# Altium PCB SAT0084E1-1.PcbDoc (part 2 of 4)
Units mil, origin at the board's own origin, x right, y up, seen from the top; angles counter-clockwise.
Board outline 7055 x 5555 mil, 6 copper layers (Top Layer, MidLayer1-GND, MidLayer2-HiSp, MidLayer3-GND, MidLayer4, Bottom Layer), stack 57.4 mil thick; 379 components, 207 nets, 1026 pads, 1546 vias.
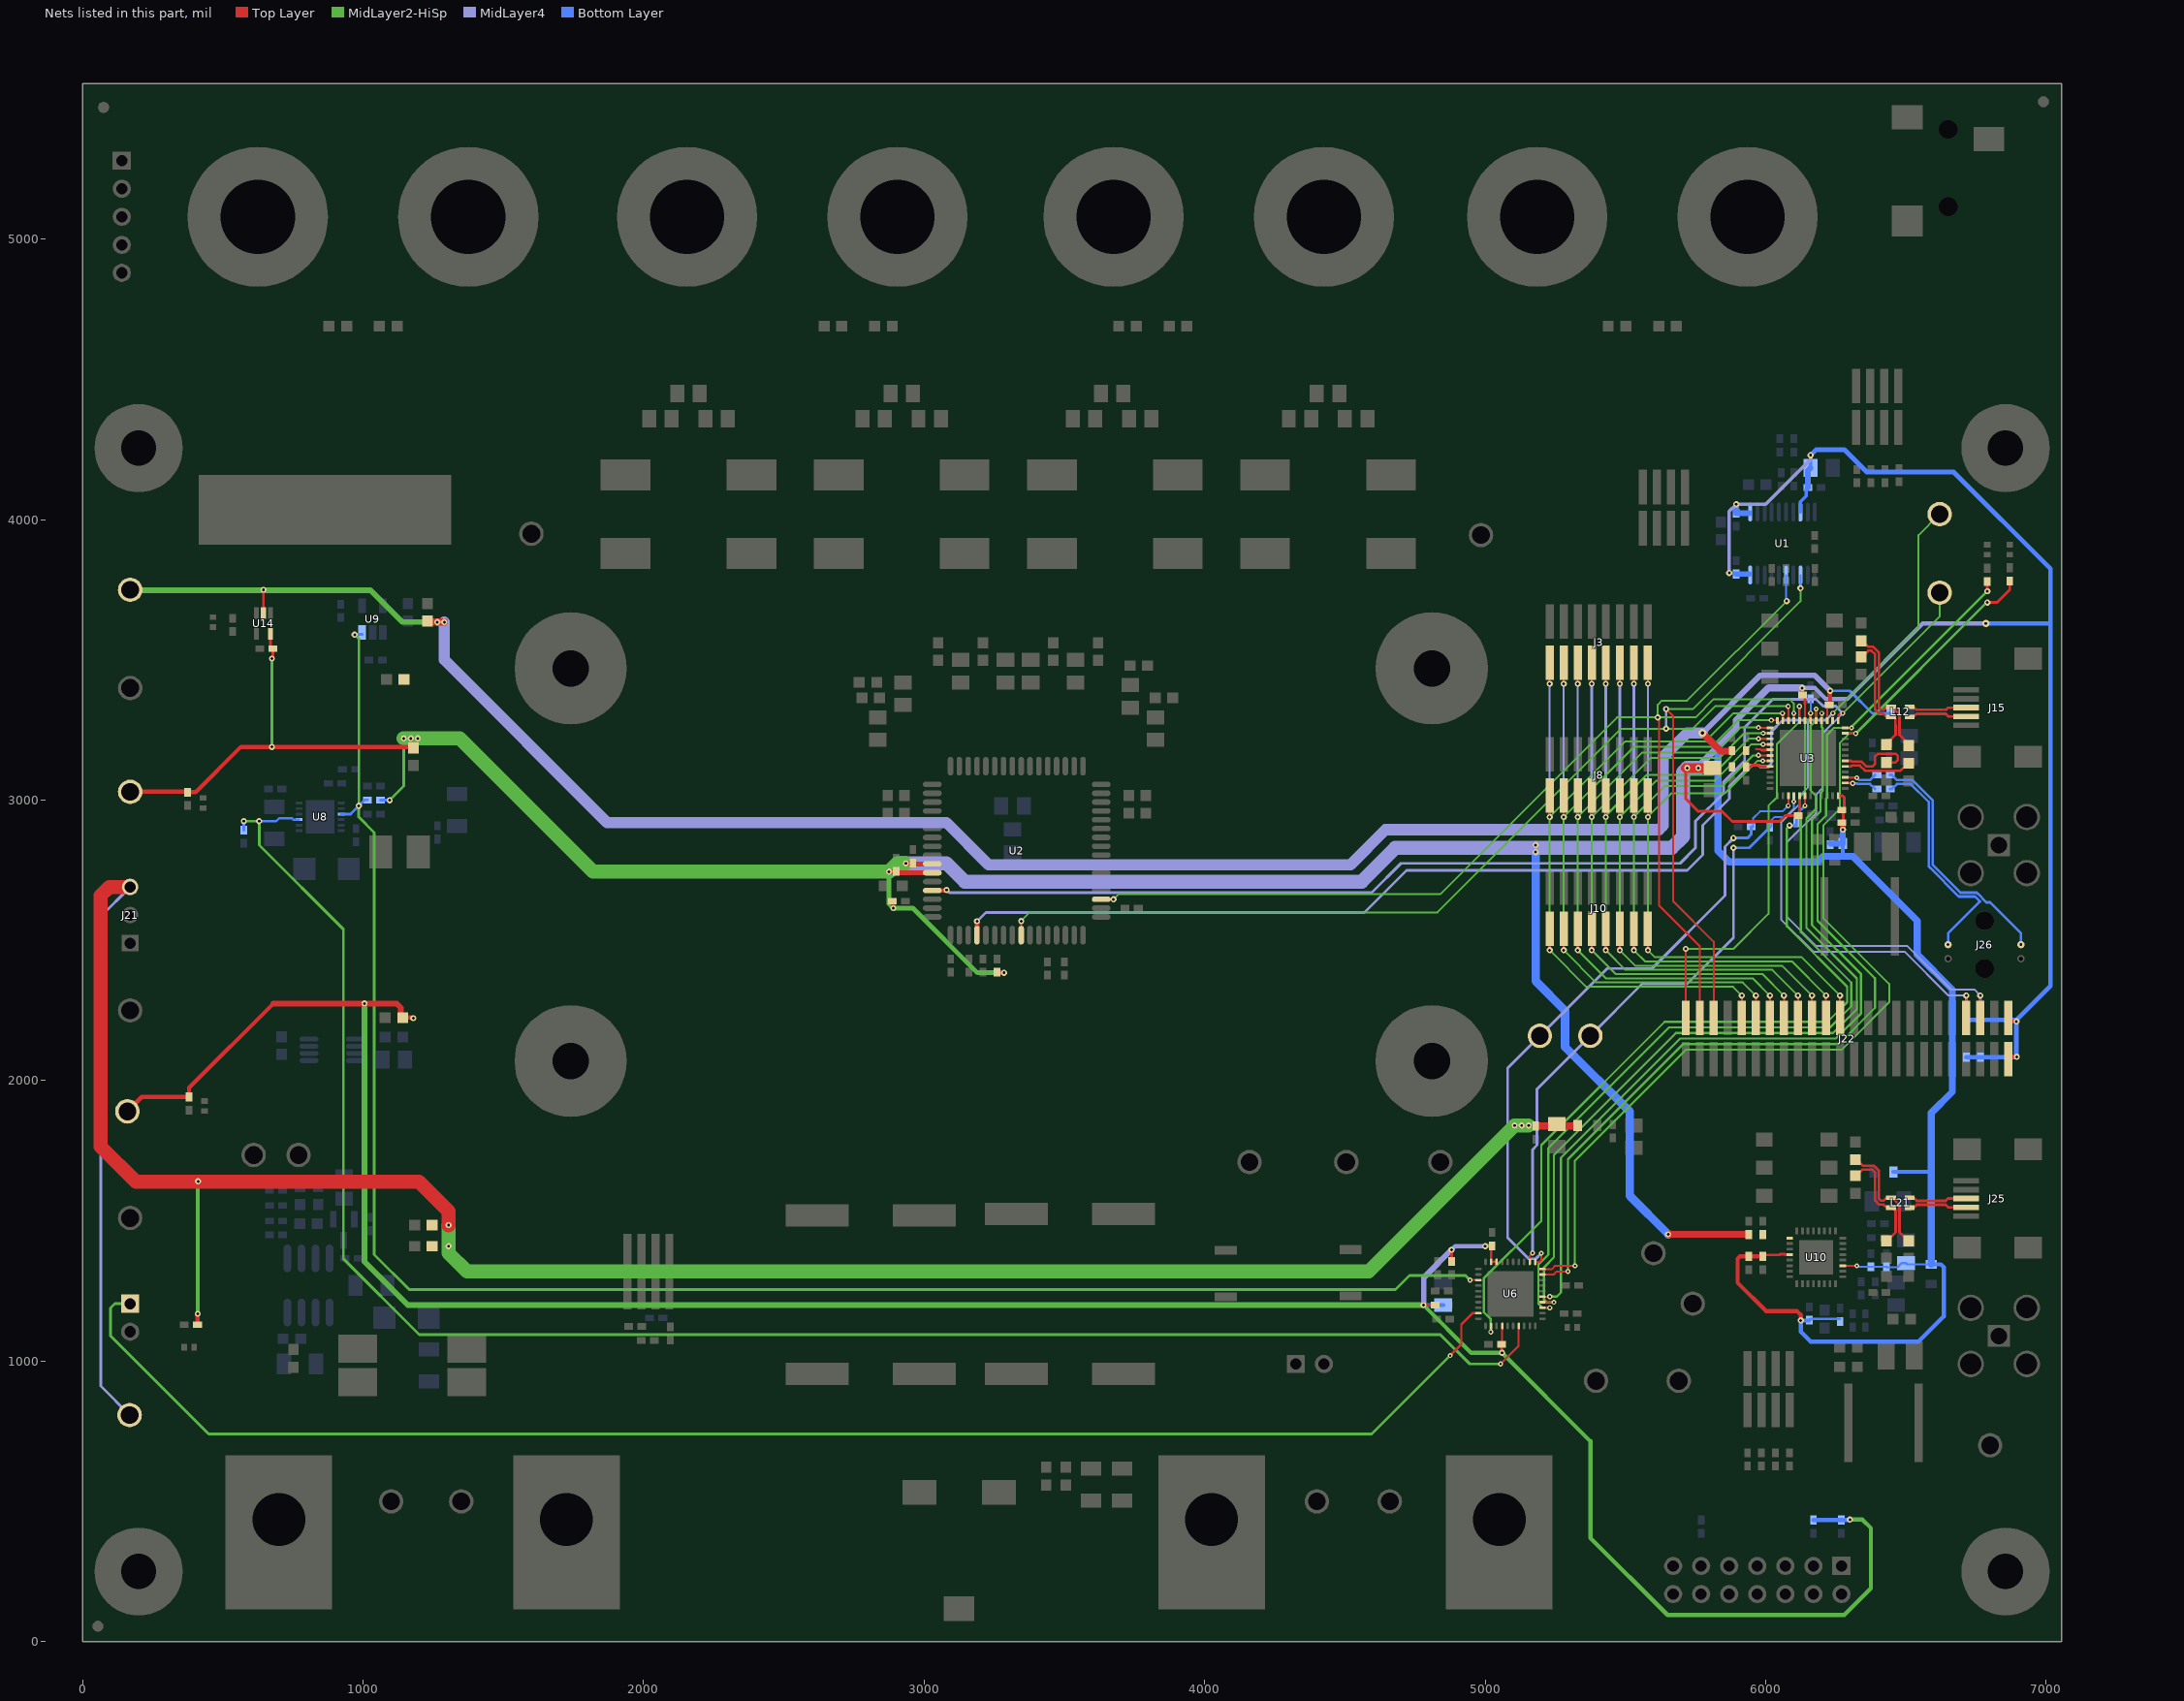
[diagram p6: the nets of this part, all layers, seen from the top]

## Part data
C1 C2 C3 C5 C18 C19 C24 C25 C43 C59 C61 C68 C71 C74 C77 C88 C96 C101 C105 C107 C112 C114 C116 C119 C127 C128: "CAP, CERM, 0.1uF, 10V, +/-10%, X7R, 0402"
C4 C87 C131: "CAP, CERM, 10uF, 10V, +/-10%, X7R, 0805"
C6 C7 C8 C9: "CAP, AL, 330uF, 50V, +/-20%, 0.12 ohm, SMD"
C10 C11 C92 C98: "CAP, CERM, 4.7uF, 50V, +/-10%, X7R, 1206"
C12: "CAP, CERM, 0.082uF, 50V, +/-10%, X7R, 0603"
C13: "CAP, CERM, 2200pF, 50V, +/-10%, X7R, 0603"
C14 C15 C16 C17: "CAP, CERM, 1uF, 25V, +/-10%, X7R, 0603"
C20 C21 C89: "CAP, CERM, 2200pF, 16V, +/-10%, X7R, 0402"
C22 C23 C102: "CAP, CERM, 2.2uF, 10V, +/-10%, X7R, 0603"
C26 C30: "CAP, CERM, 1uF, 50V, +/-10%, X7R, 0805"
C27 C32 C36 C40 C44 C48 C51 C55: "CAP, CERM, 1000pF, 50V, +/-5%, X7R, 0603"
C28 C31 C33 C37 C39 C41 C45 C47 C49 C52 C54 C56: "CAP, CERM, 0.47uF, 50V, +/-10%, X7R, 0805"
C29 C34 C38 C42 C46 C50 C53 C57: "CAP, CERM, 0.01uF, 50V, +/-5%, X7R, 0603"
C35: "CAP, CERM, 0.22uF, 16V, +/-10%, X7R, 0402"
C58 C62 C67 C69 C70 C72 C73 C76 C99 C103 C104 C108 C113 C115 C118: "CAP, CERM, 0.01uF, 16V, +/-10%, X7R, 0402"
C60 C64 C66 C75 C106 C117 C132: "CAP, CERM, 4.7uF, 16V, +/-10%, X7R, 0805"
C63 C65: "CAP, CERM, 0.1uF, 16V, +/-10%, X7R, 0402"
C78 C91 C100 C120: "CAP, CERM, 22uF, 10V, +/-10%, X7R, 1206"
C80 C81: "CAP, CERM, 0.1uF, 50V, +/-10%, X7R, 0402"
C82 C122: library part GRM188R71H104KA93D, "CAP, CERM, 0.1uF, 50V, +/-10%, X7R, 0603"
C84 C85 C124 C125 C130: "CAP, CERM, 0.1uF, 50V, +/-10%, X7R, 0603"
C86 C126: library part GRM188R71H473KA61D, "CAP, CERM, 0.047uF, 50V, +/-10%, X7R, 0603"
C90: "CAP, CERM, 1uF, 100V, +/-10%, X7R, 1206"
C93: "CAP, CERM, 150pF, 50V, +/-5%, C0G/NP0, 0603"
C94: "CAP, CERM, 0.015uF, 50V, +/-10%, X7R, 0603"
C95: "CAP, CERM, 1uF, 16V, +/-10%, X7R, 0603"
C97: "CAP, CERM, 0.022uF, 16V, +/-10%, X7R, 0402"
C109 C110 C111: "CAP, CERM, 1uF, 10V, +/-10%, X7R, 0603"
C129: library part GRM188R71C334KA01D, "CAP, CERM, 0.33uF, 16V, +/-10%, X7R, 0603"
D1: "LED, Orange, SMD"
D2 D4 D6 D7 D10: "LED, Yellow/green, SMD"
D3 D5: "Diode, Schottky, 60V, 1A, SMA"
D8: "LED, Blue, SMD"
D9: "Diode, Schottky, 30V, 0.2A, SOT-23"
FID1 FID2 FID3 FID4 FID5 FID6: "Fiducial mark.  There is nothing to buy or mount."
H1 H2 H3 H4: library part "NY PMS 440 0025 PH", "Machine Screw, Round, #4-40 x 1/4, Nylon, Philips panhead"
H5 H6 H7 H8: library part 1902C, "Standoff, Hex, 1 1/16\"L #4-40 Nylon"
H9: library part V5583K, "Heatsink, requires 2 M3 screw Mounting hole per rails"
H10 H11 H12 H13: library part "MPMS 003 0005 PH", "MACHINE SCREW PAN PHILLIPS M3 10mm"
H14 H15 H16 H17: library part 1902C, "ROUND SPACER M3 PVC 1.4MM"
J1 J2 J18 J20: library part CB35-36-CY, "Terminal 50A Lug"
J3 J8 J10: library part FTS-108-02-L-DV, "Header, 8x2, 1.27mm"
J4: "Connector, Audio Jack, 3.5mm, Stereo, SMD"
J5 J13 J16 J19: library part FTS-104-02-L-DV, "Header, 4x2, 1.27mm"
J6: library part TSW-105-07-G-S, "Header, TH, 100mil, 5x1, Gold plated, 230 mil above insulator"
J7 J9 J11 J12: library part 2269-0, "Connector, Banana Jack, Double, Black Base, 15A, TH"
J14 J23: "RIGHT ANGLE PLUG FOR PCB"
J15 J25: "Connector, Receptacle, Mini-USB 2.0, Type AB, R/A, SMT"
J17: library part SBH11-PBPC-D07-ST-BK, "Header (shrouded), 100 mil, 7x2, Gold plated, TH"
J21: library part PEC03SAAN, "Header, 100mil, 3x1, Tin plated, TH"
J22: "Header, 24x2, 1.27mm"
J24 J27: library part TSW-102-07-G-S, "Header, TH, 100mil, 2x1, Gold plated, 230 mil above insulator"
J26: "Double Compliant Coax Assembly"
L1: "Inductor, Shielded E Core, Ferrite, 10uH, 7.2A, 0.01 ohm, SMD"
L2 L3 L4 L5: "Inductor, Shielded, Ferrite, 10uH, 3A, 0.022 ohm, SMD"
L6 L7 L8 L16 L17: library part BEAD-BLM18AG_SERIES, "Ferrite Chip, 400 mA, ±25%"
L9: library part MSS7341T-104MLB, "Inductor, Shielded Drum Core, Ferrite, 100uH, 0.7A, 0.28 ohm, SMD"
L10 L19: library part IND_1008PS-XXXMC, "Inductor, 5.6uH, 1.5A, 0.36 ohm, SMD"
L11 L20: "Inductor, Wirewound, Ferrite, 165uH, 0.65A, 0.46 ohm, SMD"
L12 L21: library part DLW21SN900HQ2L, "Coupled inductor, 0.3A, 0.4 ohm, +/-25%, SMD"
L13: "Coupled inductor, 68uH, 1.35A, 0.2 ohm, +/-20%, SMD"
L14: "Inductor, Shielded, Ferrite, 10uH, 1.05A, 0.083 ohm, SMD"
L18: "Inductor, Shielded Drum Core, Ferrite, 100uH, 0.7A, 0.28 ohm, SMD"
LBL1: library part THT-14-423-10, "Thermal Transfer Printable Labels, 0.650\" W x 0.200\" H - 10,000 per roll"
Logo1: library part TI_Logo, "Texas Instrument Corporate Signature"
R1 R2 R4 R5 R6 R19 R20 R25 R32 R43 R48 R54 R59 R74 R92 R107: "RES, 10k ohm, 5%, 0.063W, 0402"
R3: "RES, 133 ohm, 1%, 0.063W, 0402"
R7 R8: "RES, 470 ohm, 5%, 0.063W, 0402"
R9: "RES, 20k ohm, 5%, 0.063W, 0402"
R10 R21 R22 R41: "RES, 47k ohm, 5%, 0.063W, 0402"
R11 R12 R13 R14 R15 R16 R17 R18: "RES, 5.60 ohm, 1%, 0.33W, 0805"
R23 R24 R72 R73: "RES, 4.7k ohm, 5%, 0.063W, 0402"
R26 R27: library part CRCW0402220RJNED, "RES, 220 ohm, 5%, 0.063W, 0402"
R28: "RES, 220 ohm, 5%, 0.063W, 0402"
R29 R30 R86 R87: "RES, 1.0k ohm, 5%, 0.1W, 0603"
R31 R88: library part CRCW06030000Z0EA, "RES, 0 ohm, 5%, 0.1W, 0603"
R33 R37 R44 R45 R58 R64 R65 R93 R95 R108: "RES, 0 ohm, 5%, 0.1W, 0603"
R34: "RES, 475 ohm, 1%, 0.063W, 0402"
R35 R62 R66 R67: "RES, 365 ohm, 1%, 0.063W, 0402"
R36 R89 R97 R99: "RES, 10.0k ohm, 1%, 0.063W, 0402"
R38 R91: "RES, 0 ohm, 5%, 0.063W, 0402"
R39: "RES, 11.0k ohm, 1%, 0.063W, 0402"
R40 R47 R96: "RES, 49.9 ohm, 1%, 0.063W, 0402"
R46: "RES, 1.0 ohm, 5%, 0.1W, 0603"
R49: "RES, 1.96k ohm, 1%, 0.063W, 0402"
R50: "RES, 11.5k ohm, 1%, 0.1W, 0603"
R51 R63: "RES, 9.76k ohm, 1%, 0.063W, 0402"
R52: "RES, 1.82k ohm, 1%, 0.063W, 0402"
R53: "RES, 28.0k ohm, 1%, 0.063W, 0402"
R56: "RES, 44.2k ohm, 1%, 0.063W, 0402"
R57 R94: "RES, 100k ohm, 5%, 0.063W, 0402"
R60: "RES, 3.16k ohm, 1%, 0.063W, 0402"
R61: "RES, 0.39 ohm, 1%, 0.125W, 0402"
R90: "RES, 2.00k ohm, 1%, 0.063W, 0402"
R98: "RES, 5.36k ohm, 1%, 0.063W, 0402"
R100: "RES, 18.7k ohm, 1%, 0.063W, 0402"
R103 R105: "RES, 100k ohm, 1%, 0.063W, 0402"
R104: "RES, 3.01k ohm, 1%, 0.063W, 0402"
R106: "RES, 14.0k ohm, 1%, 0.063W, 0402"
S1 S5: library part SKRKAEE010, "Switch, Push Button, SMD"
SH-J3 SH-J5 SH-J8 SH-J10 SH-J13 SH-J16 SH-J19 SH-J22a SH-J22b SH-J22c SH-J22d SH-J22e SH-J22f SH-J22g SH-J22h SH-J22i SH-J22j SH-J22k SH-J22l SH-J22m SH-J22n SH-J22o SH-J22p SH-J22q SH-J22r SH-J22s SH-J22t SH-J22u SH-J22v SH-J22w SH-J22x: "CONN JUMPER SHORTING 1.27MM GOLD"
SH-J21 SH-J24 SH-J27: "Shunt, 100mil, Gold plated, Black"
TP1 TP10 TP11 TP15 TP16 TP18 TP19: library part 5005, "Test Point, Compact, Red, TH"
TP2 TP3 TP4 TP9 TP14 TP17 TP41 TP48: library part 5006, "Test Point, Compact, Black, TH"
TP5 TP6 TP7 TP8 TP23 TP24 TP37 TP38 TP54 TP55: library part 5007, "Test Point, Compact, White, TH"
TP12: library part 5009, "Test Point, Compact, Yellow, TH"
TP13: library part 5008, "Test Point, Compact, Orange, TH"
U1: "2-VRMS DirectPath™, 112, 106, 100-dB Audio Stereo DAC with 32-bit, 384-kHz PCM Interface, PW0020A"
U2: library part "Digital Input Four-Channel Automotive Digital Amplifier", "There is nothing to buy or mount."
U3: "IC SER/DESER 10-50MHZ 8B 48-WQFN"
U6: "MSP430F22x2  Automotive  Mixed-Signal  Microcontrollers"
U7: "LM5001x  High-Voltage  Switch-Mode  Regulator"
U8: "LM34919C Ultra Small 42V, 600 mA Constant On-Time Buck Switching Regulator, DNT0012B"
U9: "LDO Voltage Regulators Ultra Lo Noise Hi PSRR Fast RF 200mA"
U10: "Multi-Channel Digital Audio Link, RTV0032A"
U13: library part LM2936MM-3.3/NOPB, "Ultra-Low Quiescent Current LDO Voltage Regulator, 8-pin Mini SOIC, Pb-Free"
U14: "IC BUS BUFF GATE 3ST SGL SC70-5"
ZZ1: library part AssemblyNoteLabel
ZZ2 ZZ3 ZZ4 ZZ5 ZZ6 ZZ7: library part AssemblyNote

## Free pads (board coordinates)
  round 400 / inner round 200 / far side round 400 hole 130: 0(1740,2070) 0(1740,3470) 0(4810,2070) 0(4810,3470)

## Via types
v1: diameter 22, hole 10, Top Layer to Bottom Layer, tented both sides, 1179 vias
v2: diameter 48, hole 22, Top Layer to Bottom Layer, tented both sides, 128 vias
v3: diameter 32, hole 16, Top Layer to Bottom Layer, tented both sides, 112 vias
v4: diameter 18, hole 8, Top Layer to Bottom Layer, tented both sides, 80 vias
v5: diameter 19.68, hole 7.87, Top Layer to Bottom Layer, tented both sides, 30 vias
v6: diameter 26, hole 16, Top Layer to Bottom Layer, 12 vias
v7: diameter 36, hole 16, Top Layer to Bottom Layer, tented both sides, 2 vias
v8: diameter 26, hole 10, Top Layer to Bottom Layer, tented both sides, 1 vias
v9: diameter 20, hole 8, Top Layer to Bottom Layer, tented both sides, 1 vias
v10: diameter 30, hole 12, Top Layer to Bottom Layer, tented both sides, 1 vias

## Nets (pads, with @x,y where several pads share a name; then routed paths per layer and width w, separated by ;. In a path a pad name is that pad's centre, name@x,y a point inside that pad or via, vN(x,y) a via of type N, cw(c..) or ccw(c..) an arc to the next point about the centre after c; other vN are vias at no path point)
1V8: C58.1 C59.1 C67.1 C68.1 C70.1 C71.1 C104.1 C105.1 C106.1 C113.1 C114.1 L7.1 L8.1 L16.1 L17.1 R36.2 R65.2 R89.2 R92.2 TP18.1 U3.3 U3.17 U3.36 U10.11 U10.28 U14.2 | length 12576.4
  Top Layer w7: 5965,3183 5966,3182 ; 5983.79,3178.21 5986,3178.21 ; U3.3@6218.9,3283.86 6219.5,3284.46 6219.5,3333.12 C70.1@6226.38,3340
  Top Layer w8: 5966,3182 5980,3182 5983.79,3178.21 ; U10.11@6274.49,1340.47 6274.96,1340 v4(6325,1340)
  Top Layer w10: U14.2@645,3675 v1(645,3750) ; 5986,3178.21 5999.49,3178.21 6000.8,3179.53 U3.17@6016.14,3179.53 ; C113.1@5990,1373.62 5995.38,1379 6048.7,1379 6049.7,1380 6050.3,1380 6051.3,1381 6069,1381 6070.16,1379.84 U10.28@6085.51,1379.84 ; U3.36@6258.27,3016.14 6273.86,3016.14 6280,3010 6280,2968.62 6276.38,2965 C68.1@6276.38,2920
  Top Layer w15: C113.1@5990,1373.62 C114.1@5940,1373.62 5908.62,1373.62 5900,1365 5900,1280 6001,1179 6111,1179 6125,1165 v1@6125,1150 ; v1@6225,3390 6230,3385 6230,3343.62 C70.1@6226.38,3340
  Top Layer w20: v1(6275,2895) 6275,2918.62 C68.1@6276.38,2920
  Top Layer w25: R65.2@1230,3638.5 1233.5,3635 v1(1265,3635) v1(1290,3635) ; v10(5775,3240) 5840,3175 5878.62,3175 C59.1@5880,3176.38
  MidLayer2-HiSp w20: TP18.1@170,3748.62 1026.38,3748.62 1140,3635 v1@1261.5,3635
  MidLayer4 w20: v10(5775,3240) 5980,3445 6175,3445 v1@6225,3395
  MidLayer4 w25: v1(1265,3635) v1(1290,3635)
  MidLayer4 w40: v1(1290,3635) 1290,3500 1870,2920 3080,2920 3230,2770 4520,2770 4645,2895 5620,2895 5635,2910 5635,3155 5720,3240 v10(5775,3240)
  Bottom Layer w8: R89.2@6155,1146.38 6159.43,1150.81 6264.43,1150.81 R92.2@6265,1151.38 ; v4(6325,1340) 6328.62,1336.38 C104.1@6375,1336.38 C105.1@6430,1336.38 6431.38,1335 6470,1335 6485,1350 C106.1@6500,1350 6505,1345 L16.1@6590,1345
  Bottom Layer w10: C71.1@6226.38,3340 6226.38,3388.62 6225,3390 6300,3390 6380,3310 L7.1@6445,3310
  Bottom Layer w15: R89.2@6155,1146.38 6153.62,1145 v1(6125,1145) 6125,1105 6160,1070 6545,1070 6635,1160 6635,1335 6625,1345 L16.1@6590,1345 ; 6275,2800 L8.1@6275,2845 ; L17.1@6455,1675 6590,1675
  Bottom Layer w20: R36.2@6230,2846.38 6231.38,2845 L8.1@6275,2845 v1(6275,2895)
  Bottom Layer w25: v10(5775,3240) 5830,3185 5830,2820 5870,2780 6185,2780 6205,2800 6275,2800 6310,2800 6540,2570 6540,2450 6665,2325 6665,1960 6590,1885 6590,1675 L16.1@6590,1345
  other v1: 6230,3390
3V3: C1.1 C2.1 C3.1 C4.1 C5.1 C18.1 C60.1 C61.1 C62.1 C69.1 C72.1 C107.1 C108.1 C112.1 J22.47 J22.48 R21.2 R22.2 R23.2 R24.2 R58.2 R59.1 R62.2 R64.1 R72.2 R73.2 TP16.1 U1.1 U1.8 U1.20 U2.58 U2.59 U3.7 U3.20 U3.29 U10.25 U14.5 | length 16477.5
  Top Layer w7: U3.7@6140.5,3284.2 6140.5,3343.83
  Top Layer w8: C72.1@6118.62,2945 6120,2946.38 6120,3015.67 U3.29@6120.47,3016.14
  Top Layer w9: U14.5@670,3595 670,3548.62 C112.1@678.62,3540 ; v1(675,3505) 678.62,3508.62 C112.1@678.62,3540 ; C112.1@675,3536.38 C112.1@678.62,3540 ; 5970,3125 5974.99,3125 5980.49,3119.5 6015.17,3119.5 U3.20@6016.14,3120.47 ; C62.1@6133.62,3375 6140.16,3368.46 6140.16,3344.18 6140.5,3343.83 ; U3.7@6140.16,3283.86 U3.7@6140.5,3284.2
  Top Layer w10: v1@5715,3115 5715,3005 5760,2960 5845,2960 5881,2924 6049,2924 6070,2945 C72.1@6116.38,2945 ; C69.1@5934.38,3123 C69.1@5930,3118.62 5943.62,3118.62 5950,3125 5970,3125
  Top Layer w15: TP16.1@170,3030 373.62,3030 R62.2@375,3028.62 403.62,3028.62 565,3190 v1(675,3190) 1165,3190 R58.2@1175,3180 ; v1(6130,3400) 6130,3378.62 C62.1@6133.62,3375 ; J22.47@6865,2076.48 J22.47@6872.15,2083.62 ; J22.48@6865,2223.52 J22.48@6872.15,2216.38 ; J22.47@6872.15,2085 v1(6895,2085) ; J22.48@6872.15,2211.38 v1(6893.62,2211.38)
  Top Layer w17: v1(2875,2745) 2898.62,2745 C5.1@2900,2746.38 ; R22.2@2886.38,2640 2890,2636.38 v1(2890,2615) ; C5.1@2900,2751.38 C5.1@2900,2746.38 ; v1(2935,2775) 2958.62,2775 C18.1@2960,2776.38 ; C18.1@2960,2772.76 U2.58@3029.13,2772.76 ; U2.59@3029.13,2741.26 2900,2741.26 C5.1@2900,2746.38 ; R21.2@3260,2386.38 3261.38,2385 v1(3285,2385)
  Top Layer w25: v1(5652.5,1452.5) 5938.88,1452.5 C107.1@5940,1451.38
  Top Layer w35: v1@5715,3115 C60.1@5810,3115
  MidLayer2-HiSp w9: v1(675,3190) v1(675,3505)
  MidLayer2-HiSp w10: v1(1095,3000) 1145,3050 v1(1145,3220)
  MidLayer2-HiSp w17: v1(2875,2745) 2875,2630 v1(2890,2615) 2960,2615 3190,2385 v1(3285,2385)
  MidLayer2-HiSp w50: v1(1145,3220) v1(1170,3220) v1(1195,3220) ; v1@1205,3220 1345,3220 1820,2745 v1(2875,2745) 2905,2775 v1(2935,2775)
  MidLayer4 w12: v1(5870,3810) 5870,4030 v1(5895,4055) 6000,4055 6160,4215 v1(6160,4230)
  MidLayer4 w15: v1(6130,3400) 6175,3400 6215,3360 6290,3360 6560,3630 v8(6785,3630)
  MidLayer4 w25: v1@5755,3115 5895,3255 5895,3285 6010,3400 v1(6130,3400)
  MidLayer4 w50: v1(2875,2745) 2905,2775 v1(2935,2775) 3080,2775 3145,2710 4560,2710 4680,2830 5665,2830 5705,2870 5705,3100 v1(5720,3115) v1(5760,3115)
  Bottom Layer w10: R59.1@1062.81,3000.56 1094.44,3000.56 v1(1095,3000)
  Bottom Layer w12: v1(5870,3810) 5891.38,3810 C2.1@5895,3806.38 ; U1.8@6123.98,4027.2 6123.98,4063.98 6145,4085 6145,4110 C3.1@6150,4115 ; C4.1@6160,4185 v1(6160,4230)
  Bottom Layer w15: R72.2@6715,2083.62 R73.2@6765,2083.62 v1@6895,2083.62 ; R23.2@6715,2216.38 R24.2@6765,2216.38 6893.62,2216.38 v1@6895,2215 ; v8(6785,3630) 7015,3630
  Bottom Layer w17: v1(6160,4230) 6180,4250 6280,4250 6360,4170 6670,4170 7015,3825 7015,2337.76 6893.62,2216.38 v1@6893.62,2085
  Bottom Layer w20: C2.1@5895,3806.38 U1.20@5941.26,3806.38 ; v1(5895,4055) C1.1@5895,4023.62 U1.1@5941.26,4023.62 ; C3.1@6150,4115 6150,4175 C4.1@6160,4185
  Bottom Layer w30: v1(5180,2840) 5180,2355 5285,2250 5285,2120 5515,1890 5515,1590 v1(5652.5,1452.5)
  other v1: 5180,2815
3V3_ENA: R57.2 U6.17 U8.3 | length 6362.4
  Top Layer w7: v4(5055,990) 5119,1054 5119,1083 5119.53,1083.53 U6.17@5119.53,1125.83
  MidLayer2-HiSp w10: v1(575,2925) v1(630,2925) 630,2840 930,2540 930,1365 1200,1095 4840,1095 4945,990 v4(5055,990)
  Bottom Layer w8: v1(630,2925) 691,2925 702,2936 747,2936 752.29,2930.71 U8.3@772.1,2930.71
  Bottom Layer w10: R57.2@575,2893.62 v1(575,2925)
3V3_MCU: C87.1 C88.1 C128.1 R26.1 R27.1 R41.2 R43.2 R45.2 R66.2 TP19.1 U6.14 U6.38 U6.39 | length 9449.8
  Top Layer w8: v1@5058.62,1031.38 v1(5060,1030) ; C128.1@5058.62,1060 5060.47,1061.85 U6.14@5060.47,1125.83
  Top Layer w9: C88.1@5021.1,1417.48 5021.1,1411.38 U6.39@5021.1,1354.17 U6.38@5040.79,1354.17
  Top Layer w10: v1(4780,1200) R41.2@4821.38,1200 R41.2@4826.38,1200 ; R43.2@4880,1355.28 v1(4880,1397) ; v1@5058.62,1031.38 C128.1@5058.62,1060
  Top Layer w15: TP19.1@159.87,1890.5 211.61,1942.24 R66.2@380,1942.24 380,1975 680,2275 ; R45.2@1135,2231.5 R45.2@1141.5,2225 1177,2225 v1(1179,2223) ; v1(5000,1410) 5001.38,1411.38 5021.1,1411.38 C88.1@5025,1411.38
  Top Layer w20: 680,2275 1120,2275 1135,2260 R45.2@1135,2231.5
  MidLayer2-HiSp w15: v1(4780,1200) 4950,1030 v1(5060,1030) 5375,715 5375,370 5650,95 6280,95 6375,190 6375,405 6345,435 v1(6300,435)
  MidLayer2-HiSp w20: v1(1005,2275) 1005,1355 1160,1200 v1(4780,1200) v1@4781,1201
  MidLayer4 w15: v1(4880,1397) 4893,1410 v1(5000,1410)
  MidLayer4 w20: v1@4781,1201 4781,1298 v1(4880,1397)
  Bottom Layer w15: v1(4780,1200) C87.1@4850,1200 ; R27.1@6170,433.62 R26.1@6270,433.62 6298.62,433.62 v1(6300,435)
3V3_PGD: R59.2 U6.3 U8.9 U9.3 | length 6395.7
  Top Layer w7: v4(4945.83,1289.21) U6.3@4975.83,1289.21
  MidLayer2-HiSp w9: v1(970,3590) 985,3575 v1(985,2980)
  MidLayer2-HiSp w10: v1(985,2980) 985,2940 1040,2885 1040,1380 1165,1255 4680,1255 4730,1305 4930.04,1305 v4(4945.83,1289.21)
  Bottom Layer w9: U8.9@921.71,2950.4 955.4,2950.4 v1(985,2980) 1005.56,3000.56 R59.2@1015.57,3000.56 ; v1(970,3590) 971.17,3591.17 U9.3@996.76,3591.17
8V: C63.1 C64.1 C129.1 J21.3 L6.1 R49.2 R108.2 TP11.1 | length 9223.2
  Top Layer w15: R49.2@409.82,1130 409.82,1167.82 v1(411,1169)
  Top Layer w25: C63.1@5180,1838.62 5323.62,1838.62 L6.1@5330,1845
  Top Layer w50: J21.3@169.87,2690.5 95.5,2690.5 65,2660 65,1765 190,1640 1200,1640 1305,1535 v1(1305,1485)
  MidLayer2-HiSp w15: v1(411,1169) 411,1640 v1(412,1641)
  MidLayer2-HiSp w50: v1(1305,1485) v1(1305,1410) 1305,1385 1370,1320 4585,1320 v1(5105,1840) v1(5130,1840) v1(5155,1840)
  MidLayer4 w10: TP11.1@168,808 65,911 65,2585.64 J21.3@169.87,2690.5
8V_ENA: J24.1 U6.9 | length 5417.2
  Top Layer w8: v4(4875,1020) 4915,1060 4915,1131 4955.1,1171.1 U6.9@4975.83,1171.1
  MidLayer2-HiSp w10: J24.1@170,1205 115,1205 100,1190 100,1090 450,740 4595,740 v4(4875,1020)
CMLOUT_N: C81.2 U3.39 | length 117.4
  Top Layer w9: U3.39@6283.86,3081.1 6320,3081.1 6321.1,3080 v4(6325,3080)
  Bottom Layer w9: v4(6325,3080) 6333,3072 6372,3072 C81.2@6390,3090
CMLOUT_P: C80.1 U3.38 | length 113
  Top Layer w9: U3.38@6283.86,3061.42 v4@6308.58,3061.42
  Bottom Layer w9: v4(6310,3060) 6325.2,3060 6327.2,3058 6372,3058 C80.1@6390,3040
CMLOUTC_N: C81.1 J26.1 | length 875.2
  Bottom Layer w9: C81.1@6443.62,3090 6450,3090 6468,3072 6523,3072 6594.9,3000.1 6594.9,2769.9 6694.3,2670.5 6752.3,2670.5 6756.4,2666.4 6787,2635.8 6799.2,2635.8 6909.92,2525.08 J26.1@6909.92,2485.04
CMLOUTC_P: C80.2 J26.2 | length 837.4
  Bottom Layer w9: C80.2@6443.62,3040 6450,3040 6468,3058 6517.2,3058 6580.9,2994.3 6580.9,2764.1 6585,2760 6688.5,2656.5 6746.5,2656.5 6764,2639 6650.08,2525.08 J26.2@6650.08,2485.04
DESER_BISTEN: R19.1 U3.6 U6.23 | length 3146.8
  Top Layer w7: U6.23@5204.17,1190.79 5229.21,1190.79 v4(5230,1190) ; U3.6@6159.84,3283.86 6159.84,3309.84 v4(6160,3310)
  MidLayer2-HiSp w8: v4(5230,1190) 5205,1190 5190,1205 5190,1345 5225,1380 5225,1760 5655,2190 6230,2190 6305,2265 6305,2350 6125,2530 6125,2945 6120,2950 6120,3010 6140,3030 6140,3275 6160,3295 v4(6160,3310)
  Bottom Layer w7: v4(6160,3310) R19.1@6160,3361.38
DESER_DIN_N: C85.1 C86.1 U3.42 | length 291.8
  Top Layer w9: U3.42@6283.86,3140.16 6304,3140.16 6306.84,3137.31 6341.48,3137.31 6358.8,3120 6380,3120 6390,3130 6390,3156 6399,3165 6464,3165 6471,3158 6471,3143 6462.5,3134.5 C85.1@6430,3134.5
DESER_DIN_P: C82.1 C84.1 U3.41 | length 240.3
  Top Layer w9: U3.41@6283.86,3120.47 6304,3120.47 6306.84,3123.31 6335.69,3123.31 6354,3105 6480,3105 ; 6485,3110 6480,3105 ; C82.1@6500,3125 6480,3105
DESER_GPI2: R20.1 TP54.1 U3.27 U6.31 | length 2367.6
  Top Layer w7: U6.31@5178.58,1354.17 5194.17,1354.17 5200,1360 v4(5200,1385) ; v4(6080,2980) 6080.5,2980.5 6080.5,3015.54 U3.27@6081.1,3016.14
  MidLayer4 w10: v4(5200,1385) 5180,1365 5155,1365 5080,1440 5080,2045 TP54.1@5195,2160 5435,2400 5595,2400 5855,2660 5855,2835 v1(5885,2865)
  Bottom Layer w7: R20.1@5955,2903.62 5955,2935 5980,2960 6060,2960 v4(6080,2980)
  Bottom Layer w10: v1(5885,2865) 5935,2865 5948.62,2878.62 R20.1@5948.62,2905
DESER_GPI3: R54.1 TP55.1 U3.28 U6.32 | length 2201.5
  Top Layer w7: U6.32@5158.9,1354.17 5158.9,1375.9 v4(5169,1386) ; v4(6100,2995) 6100.79,2995.79 U3.28@6100.79,3016.14
  MidLayer4 w10: v4(5169,1386) 5169,1754 5185,1770 5185,1970 TP55.1@5375,2160 5560,2345 5720,2345 5885,2510 v1(5885,2830)
  Bottom Layer w7: R54.1@6015,2903.62 6020,2908.62 6020,2928.62 6031.38,2940 6070,2940 6099.5,2969.5 6099.5,2994.5 v4(6100,2995)
  Bottom Layer w10: v1(5885,2830) 5941.38,2830 R54.1@6015,2903.62
DESER_I2C_SCL: J22.42 R23.1 TP7.1 U2.4 U3.2 | length 6106.2
  Top Layer w7: U3.2@6238.58,3283.86 v4@6238.58,3309.58 ; J22.42@6715,2223.52 v1(6715,2303.52)
  Top Layer w10: v4@6238.58,3309.58 v4(6239,3310)
  Top Layer w17: U2.4@3188.58,2518.82 v1(3188.58,2568.58) v1@3190,2570
  MidLayer2-HiSp w7: v4(6239,3310) 6545,3616 6545,3945 TP7.1@6620,4020
  MidLayer4 w7: 6152,3285 6150,3283 6150,3045 6120,3015 6120,2985 6055,2920 6055,2575 6170,2460 6495,2460 6651.48,2303.52 v1(6715,2303.52)
  MidLayer4 w10: v1(3188.58,2568.58) 3220,2600 4570,2600 4720,2750 5720,2750 5775,2805 5775,2910 5870,3005 5870,3050 5945,3125 5975,3125 5981,3119 6009,3119 6020,3130 6020,3245 6060,3285 6214,3285 v4(6239,3310)
  Bottom Layer w10: R23.1@6715,2263.62 v1(6715,2303.52)
DESER_I2C_SDA: J22.44 R24.1 TP8.1 U2.61 U3.1 | length 6052.8
  Top Layer w7: U3.1@6258.27,3283.86 6258.5,3284.09 6258.5,3303.5 6265,3310 v4(6275,3310) ; J22.44@6765,2223.52 v1(6765,2303.52)
  Top Layer w15: U2.61@3029.13,2678.27 3078.27,2678.27 v1(3080,2680)
  MidLayer2-HiSp w7: v4(6275,3310) 6620,3655 TP8.1@6620,3740
  MidLayer4 w7: v4(6275,3310) 6202,3237 6202,3042 6180,3020 6180,2955 6075,2850 6075,2585 6180,2480 6505,2480 6660,2325 6706.07,2325 ; 6706.09,2325.02 6723.91,2325.02 ; 6723.93,2325 6743.52,2325 v1(6765,2303.52)
  MidLayer4 w10: v1(3080,2680) 3090,2670 4595,2670 4700,2775 5695,2775 5750,2830 5750,2925 5850,3025 5850,3065 5925,3140 5925,3260 6025,3360 6180,3360 6205,3335 6250,3335 v4(6275,3310)
  Bottom Layer w10: R24.1@6765,2263.62 v1(6765,2303.52)
DESER_I2S_BCK: J22.6 U1.13 U2.9 U3.10 | length 5129.7
  Top Layer w7: v1@3345,2570 v1(3346.06,2568.94) U2.9@3346.06,2518.82 ; v1(5645,3325) 5670,3300 5670,2640 5815,2495 J22.6@5815,2223.52 ; v4(6080,3335) 6080.5,3334.5 6080.5,3284.46 U3.10@6081.1,3283.86
  MidLayer2-HiSp w7: v1(3346.06,2568.94) 3377.13,2600 4830,2600 5485,3255 5740,3255 5820,3335 v4(6080,3335) ; v1(5645,3325) 5740,3325 6123.98,3708.98 v1(6123.98,3756.02)
  MidLayer4 w7: v1(5645,3255) v1(5645,3325)
  Bottom Layer w7: U1.13@6123.98,3802.8 v1(6123.98,3756.02) v1@6125,3755
DESER_I2S_DATA0: J3.1 J8.1 J10.1 J22.10 U3.11 | length 3019.8
  Top Layer w7: v1(5230,2465) J10.1@5230,2541.48 ; v1(5230,2940) J8.1@5230,3016.48 ; v1(5230,3415) J3.1@5230,3490 ; J22.10@5915,2223.52 v1(5915,2303.52) ; v4(6060,3310) 6061.42,3308.58 U3.11@6061.42,3283.86
  MidLayer2-HiSp w7: v1(5230,2465) v1(5230,2940) 5500,3210 5785,3210 5885,3310 v4(6060,3310) ; v1@5235,2460 5360,2335 5883.52,2335 v1(5915,2303.52) v1@5920,2298.52
  MidLayer4 w7: v1(5230,2940) v1(5230,3415)
DESER_I2S_DATA1: J3.3 J8.3 J10.3 J22.12 U3.12 | length 2914.9
  Top Layer w7: v1(5280,2465) J10.3@5280,2541.48 ; v1(5280,2940) J8.3@5280,3016.48 ; v1(5280,3415) J3.3@5280,3490 ; J22.12@5965,2223.52 v1(5965,2303.52) ; v4(6020,3285) 6040.59,3285 U3.12@6041.73,3283.86
  MidLayer2-HiSp w7: v1(5280,2465) v1(5280,2940) 5530,3190 5805,3190 5900,3285 v4(6020,3285) ; v1@5285,2460 5395,2350 5918.52,2350 v1(5965,2303.52) v1@5970,2298.52
  MidLayer4 w7: v1(5280,2940) v1(5280,3415)
DESER_I2S_DATA2: J3.5 J8.5 J10.5 J22.14 U3.13 | length 2830.1
  Top Layer w7: v1(5330,2465) J10.5@5330,2541.48 ; v1(5330,2940) J8.5@5330,3016.48 ; v1(5330,3415) J3.5@5330,3490 ; v4(5974,3259) 5974,3258 5974.27,3258.27 5982.69,3258.27 5982.92,3258.5 U3.13@6015.91,3258.5 ; J22.14@6015,2223.52 v1(6015,2303.52)
  MidLayer2-HiSp w7: v1(5330,2465) v1(5330,2940) 5560,3170 5820,3170 5909,3259 v4(5974,3259) v4@5974,3258 ; v1@5335,2460 5430,2365 5953.52,2365 v1(6015,2303.52) v1@6020,2298.52
  MidLayer4 w7: v1(5330,2940) v1(5330,3415)
DESER_I2S_DATA3: J3.7 J8.7 J10.7 J22.16 U3.14 | length 2771.4
  Top Layer w7: v1(5380,2465) J10.7@5380,2541.48 ; v1(5380,2940) J8.7@5380,3016.48 ; v1(5380,3415) J3.7@5380,3490 ; v4@5990,3240 v4(5991,3239) 5991.42,3238.58 U3.14@6016.14,3238.58 ; J22.16@6065,2223.52 v1(6065,2303.52)
  MidLayer2-HiSp w7: v1(5380,2465) v1(5380,2940) 5590,3150 5835,3150 5924,3239 v4(5991,3239) ; v1@5385,2460 5465,2380 5988.52,2380 v1(6065,2303.52) v1@6070,2298.52
  MidLayer4 w10: v1(5380,2940) v1(5380,3415)
DESER_I2S_DATA4: J3.9 J8.9 J10.9 J22.18 U3.15 | length 2714.5
  Top Layer w7: v1(5430,2465) J10.9@5430,2541.48 ; v1(5430,2940) J8.9@5430,3016.48 ; v1(5430,3415) J3.9@5430,3490 ; v4@5974,3218.9 U3.15@6016.14,3218.9 ; J22.18@6115,2223.52 v1(6115,2303.52)
  MidLayer2-HiSp w7: v1(5430,2465) v1(5430,2940) 5430,2945 5575,3090 5810,3090 5939,3219 v4(5974,3219) ; v1@5435,2460 5500,2395 6023.52,2395 v1(6115,2303.52) v1@6120,2298.52
  MidLayer4 w10: v1(5430,2940) v1(5430,3415)
DESER_I2S_DATA5: J3.11 J8.11 J10.11 J22.20 U3.16 | length 2654.5
  Top Layer w7: v1(5480,2465) J10.11@5480,2541.48 ; v1(5480,2940) J8.11@5480,3016.48 ; v1(5480,3415) J3.11@5480,3490 ; v4@5990,3200 v4(5990.79,3199.21) U3.16@6016.14,3199.21 ; J22.20@6165,2223.52 v1(6165,2303.52)
  MidLayer2-HiSp w7: v1(5480,2465) v1(5480,2940) 5610,3070 5820,3070 5949.21,3199.21 v4(5990.79,3199.21) ; v1@5485,2460 5535,2410 6058.52,2410 v1(6165,2303.52) v1@6170,2298.52
  MidLayer4 w10: v1(5480,2940) v1(5480,3415)
DESER_I2S_DATA6: J3.13 J8.13 J10.13 J22.22 U3.18 | length 2587.1
  Top Layer w7: v1(5530,2465) J10.13@5530,2541.48 ; v1(5530,2940) J8.13@5530,3016.48 ; v1(5530,3415) J3.13@5530,3490 ; v4@5974,3159.84 U3.18@6016.14,3159.84 ; J22.22@6215,2223.52 v1(6215,2303.52)
  MidLayer2-HiSp w7: v1(5530,2465) v1(5530,2940) 5640,3050 5845,3050 5955,3160 v4(5974,3160) ; v1@5535,2460 5570,2425 6093.52,2425 v1(6215,2303.52) v1@6220,2298.52
  MidLayer4 w10: v1(5530,2940) v1(5530,3415)
DESER_I2S_DATA7: J3.15 J8.15 J10.15 J22.24 U3.19 | length 2528.9
  Top Layer w7: v1(5580,2465) J10.15@5580,2541.48 ; v1(5580,2940) J8.15@5580,3016.48 ; v1(5580,3415) J3.15@5580,3490 ; v4(5990,3140) 5990.16,3140.16 U3.19@6016.14,3140.16 ; J22.24@6265,2223.52 v1(6265,2303.52)
  MidLayer2-HiSp w7: v1(5580,2465) v1(5580,2940) 5665,3025 5855,3025 5970,3140 v4(5990,3140) ; v1@5585,2460 5605,2440 6128.52,2440 v1(6265,2303.52) v1@6270,2298.52
  MidLayer4 w7: v1(5580,2940) v1(5580,3415)
DESER_I2S_LRCK: J22.4 U1.15 U2.19 U3.9 | length 4717.2
  Top Layer w7: U2.19@3631.5,2646.77 v1(3675,2646.77) ; v1(5615,3295) 5615,3290 5620,3285 5620,2625 5765,2480 J22.4@5765,2223.52 ; v4(6100,3310) 6100.79,3309.21 U3.9@6100.79,3283.86
  MidLayer2-HiSp w7: v1(3675,2646.77) 3693.23,2665 4840,2665 5470,3295 5750,3295 5815,3360 6085,3360 6100,3345 v4(6100,3310) ; v1(5615,3295) 5615,3340 5630,3355 5720,3355 v1(6075,3710)
  Bottom Layer w7: U1.15@6072.8,3802.8 6072.8,3712.2 v1(6075,3710)
DESER_I2S_SCK: J22.2 U3.8 | length 1432.8
  Top Layer w7: J22.2@5715,2223.52 v1(5715,2470) ; v4(6120,3335) 6120.47,3334.53 U3.8@6120.47,3283.86
  MidLayer2-HiSp w7: v1(5715,2470) 5885,2470 6010,2595 6010,2960 ; 6010,2957.35 6010,2980 6039.07,3009.07 6039.07,3199.07 6120,3280 v4(6120,3335)
DESER_LOCK: R35.2 U3.48 U6.29 | length 3728.8
  Top Layer w7: U6.29@5204.17,1308.9 5243.9,1308.9 5255,1320 v4(5295,1320) ; U3.48@6283.86,3258.27 v4@6305.73,3258.27
  Top Layer w10: v4@6305.73,3258.27 v4(6306,3258) ; v1(6790,3745) R35.2@6790,3780
  MidLayer2-HiSp w8: v4(5295,1320) 5295,1720 5705,2130 6260,2130 6390,2260 6390,2365 6185,2570 6185,2915 6215,2945 6215,3005 6219,3009 6219,3234 6243,3258 v4(6306,3258)
  MidLayer2-HiSp w10: v4@6306,3261 v1(6790,3745)
  MidLayer4 w10: v4(6306,3258) v4@6306,3261
DESER_OEN: U3.5 U6.24 | length 3122
  Top Layer w7: U6.24@5204.17,1210.47 5244.53,1210.47 v4(5245,1210) ; U3.5@6179.53,3283.86 6179.53,3324.53 v4(6180,3325)
  MidLayer2-HiSp w8: v4(5245,1210) 5220,1210 5210,1220 5210,1335 5245,1370 5245,1735 5680,2170 6240,2170 6325,2255 6325,2365 6145,2545 6145,2935 6180,2970 6180,3015 6160,3035 6160,3265 6180,3285 v4(6180,3325)
DESER_OSS_SEL: U3.4 U6.25 | length 3016.4
  Top Layer w7: U6.25@5204.17,1230.16 5229.84,1230.16 v4(5230,1230) ; U3.4@6199.21,3283.86 6199.21,3304.21 v4@6200,3305
  MidLayer2-HiSp w8: v4(5230,1230) 5255,1230 5270,1245 5270,1725 5695,2150 6250,2150 6340,2240 6340,2380 6165,2555 6165,2930 6195,2960 6195,3025 6203,3033 6203,3257 6200,3260 v4(6200,3310)
DESER_PASS: R34.2 U3.47 U6.30 | length 3796.3
  Top Layer w7: U6.30@5204.17,1328.58 5238.58,1328.58 5250,1340 v4(5320,1340) ; U3.47@6283.86,3238.58 6283.94,3238.5 6320.5,3238.5 v4(6321,3238)
  Top Layer w10: v1(6790,3705) 6825,3705 6870,3750 R34.2@6870,3781.38
  MidLayer2-HiSp w7: v4(5320,1340) 5320,1715 5715,2110 6270,2110 6440,2280 6440,2345 6205,2580 6205,2910 6265,2970 6265,3205 6298,3238 v4(6321,3238)
  MidLayer2-HiSp w10: v4(6321,3238) v1@6788,3705
  MidLayer4 w10: v1@6788,3705 v1(6790,3705)
DESER_PDB: R25.1 U3.30 U6.12 | length 2953.4
  Top Layer w7: v4(6140,2980) 6140.16,2980.16 U3.30@6140.16,3016.14
  Top Layer w8: v4@5021.1,1104 U6.12@5021.1,1125.83 U6.12@5021.1,1133.72
  MidLayer2-HiSp w8: v4(5020,1104) 5020,1150 4995,1175 4995,1295 5200,1500 5200,1770 5640,2210 6220,2210 6290,2280 6290,2335 6075,2550 6075,2900 v1@6077.5,2902.5
  Bottom Layer w8: v1(6085,2910) 6101.38,2910 R25.1@6110,2918.62 ; R25.1@6110,2908.62 R25.1@6110,2918.62 ; v4(6140,2980) 6110,2950 R25.1@6110,2918.62
DIN_N: C85.2 L12.1 R37.2 | length 432.9
  Top Layer w9: R37.2@6340,3511.5 6344.5,3511.5 6366,3533 6377.2,3533 6390,3520.2 6390,3323 6404,3309 6419,3309 6430.72,3297.28 L12.1@6446.54,3297.28 6453.72,3297.28 6462.82,3288.18 6462.82,3270.18 6463,3270 6463,3233 C85.2@6442.5,3212.5
DIN_P: C84.2 L12.4 R33.2 | length 459.2
  Top Layer w9: R33.2@6340,3568.5 6344.5,3568.5 6366,3547 6383,3547 6404,3526 6404,3329 6410,3323 6421,3323 L12.4@6433.5,3335.5 ; L12.4@6446.54,3332.72 6450.13,3332.72 6476.82,3306.03 6476.82,3275.98 6477,3275.8 6477,3233 C84.2@6497.5,3212.5
DOUT_N: C125.2 L21.1 R95.2 | length 356.1
  Top Layer w9: R95.2@6320,1661.5 6324.5,1661.5 6346,1683 6379,1683 6390,1672 6390,1573.2 6403.2,1560 6405.2,1558 6420,1558 L21.1@6433,1545 ; L21.1@6446.54,1547.28 6451.72,1547.28 6463,1536 6463,1460 C125.2@6447.45,1444.45
DOUT_P: C124.2 L21.4 R93.2 | length 391.8
  Top Layer w9: R93.2@6320,1718.5 6324.5,1718.5 6346,1697 6384.8,1697 6404,1677.8 6404,1579 6411,1572 6420,1572 L21.4@6432,1584 ; L21.4@6446.54,1582.72 6450.13,1582.72 6477,1555.84 6477,1460 6490.31,1446.69
FPD_DIN_N: J15.2 L12.2 | length 192
  Top Layer w9: L12.2@6525,3295 6538,3308 6642,3308 6650,3300 6651.5,3298.5 J15.2@6707.64,3298.5
FPD_DIN_P: J15.3 L12.3 | length 191.3
  Top Layer w9: L12.3@6525,3335 6538,3322 6642,3322 6650,3330 J15.3@6707.64,3330
FPD_DOUT_N: J25.2 L21.2 | length 187.4
  Top Layer w9: L21.2@6527,1546 6538.5,1557.5 6641.5,1557.5 6650,1549 ; 6651.5,1548.5 J25.2@6707.64,1548.5
FPD_DOUT_P: J25.3 L21.3 | length 191.8
  Top Layer w9: L21.3@6525,1585 6538.5,1571.5 6641.5,1571.5 6650,1580 J25.3@6707.64,1580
